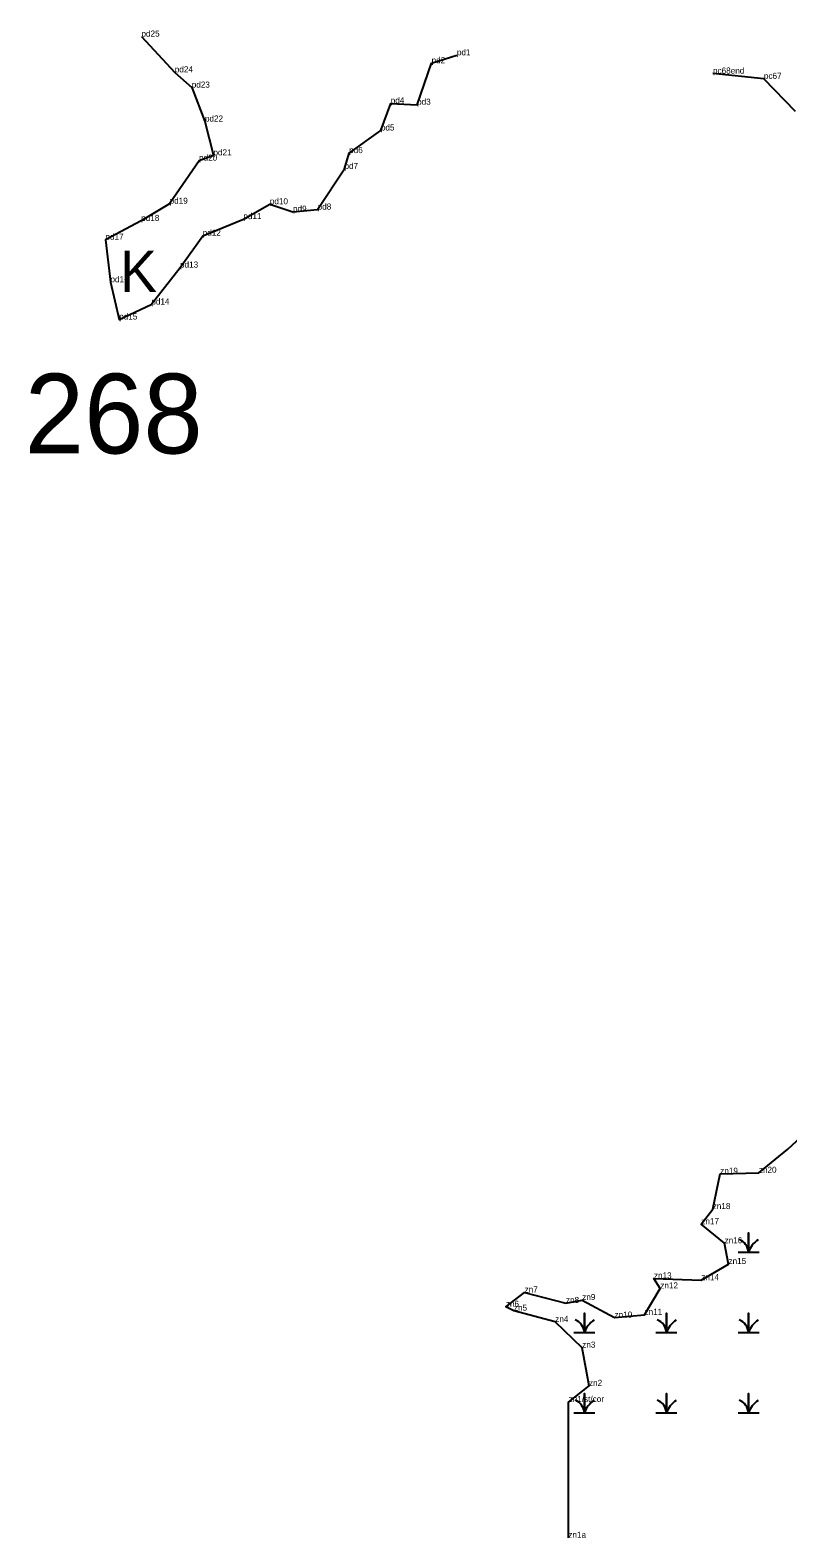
# Model space of a CAD drawing. Extents: x 2072529 to 2268796, y 436423 to 470406.
# Drawn here: x 2229846 to 2230467, y 437834 to 439069 of the extents above; entities that cross this region are included whole.
import ezdxf

# ---------------------------------------------------------------- set-up
doc = ezdxf.new("R2010")
doc.units = 0
for name, color, linetype in [('Default', 7, 'Continuous'), ('Exist Environmental Wetland Boundary', 7, 'Continuous'), ('Exist Environmental Wetland Boundary Cogo Comment', 7, 'Continuous'), ('Exist Hydro Swamp or Marsh', 7, 'Continuous'), ('Old_Level_20', 7, 'Continuous')]:
    doc.layers.add(name, color=color, linetype=linetype)

msp = doc.modelspace()

# ---------------------------------------------------------------- linework, layer by layer
at = {"layer": 'Exist Environmental Wetland Boundary'}
for points in [[(2229937.4, 439063.6), (2229964.7, 439034.3), (2229978.6, 439021.8), (2229989.4, 438994), (2229996.4, 438966.3), (2229984.6, 438962), (2229960.5, 438926.7), (2229937.2, 438912.6), (2229907.9, 438897.3), (2229912, 438862.4), (2229919.2, 438831.9), (2229945.5, 438844.2), (2229969, 438874.4), (2229987.6, 438900.5), (2230020.9, 438914.1), (2230042.6, 438926.3), (2230061.6, 438920.2), (2230081.8, 438921.9), (2230103.8, 438955.2), (2230107.6, 438968.2), (2230133.6, 438986.7), (2230141.7, 439008.9), (2230163.3, 439007.8), (2230175.2, 439041.8), (2230195.9, 439048.3)], [(2230473.4, 439002.4), (2230447.5, 439029), (2230405.8, 439033.3)], [(2230287.3, 437834.1), (2230287.5, 437945.3), (2230304.2, 437958.5), (2230298.6, 437989.8), (2230276.5, 438010.9), (2230242.6, 438020.1), (2230236, 438023.3), (2230251.4, 438035), (2230285.3, 438026.4), (2230298.6, 438028.8), (2230325.1, 438014.4), (2230349.7, 438016.7), (2230362.6, 438038.3), (2230357.4, 438046.5), (2230396.2, 438045.1), (2230418.5, 438058.3), (2230415.3, 438075.3), (2230396.2, 438090.9), (2230405.6, 438103.3), (2230411.7, 438132.2), (2230443.4, 438133), (2230467, 438152.3), (2230495.7, 438178.9)]]:
    msp.add_lwpolyline(points, dxfattribs=at)
at = {"layer": 'Exist Hydro Swamp or Marsh'}
for points in [[(2230426.3, 438068), (2230434.9, 438068), (2230434.9, 438083.8), (2230434.9, 438068), (2230443.5, 438068)], [(2230291.8, 438002.2), (2230300.4, 438002.2), (2230300.4, 438018), (2230300.4, 438002.2), (2230309, 438002.2)], [(2230359, 438002.2), (2230367.6, 438002.2), (2230367.6, 438018), (2230367.6, 438002.2), (2230376.2, 438002.2)], [(2230426.3, 438002.2), (2230434.9, 438002.2), (2230434.9, 438018), (2230434.9, 438002.2), (2230443.5, 438002.2)], [(2230291.8, 437936.4), (2230300.4, 437936.4), (2230300.4, 437952.2), (2230300.4, 437936.4), (2230309, 437936.4)], [(2230359, 437936.4), (2230367.6, 437936.4), (2230367.6, 437952.2), (2230367.6, 437936.4), (2230376.2, 437936.4)], [(2230426.3, 437936.4), (2230434.9, 437936.4), (2230434.9, 437952.2), (2230434.9, 437936.4), (2230443.5, 437936.4)]]:
    msp.add_lwpolyline(points, dxfattribs=at)
for centre, radius, start, end in [((2230422.6, 438067.1), 12.3, 4.1403, 67.535), ((2230453.1, 438061.9), 19.2, 122.1274, 161.6222), ((2230288.1, 438001.3), 12.3, 4.1403, 67.535), ((2230318.6, 437996.1), 19.2, 122.1274, 161.6222), ((2230355.4, 438001.3), 12.3, 4.1403, 67.535), ((2230385.9, 437996.1), 19.2, 122.1274, 161.6222), ((2230422.6, 438001.3), 12.3, 4.1403, 67.535), ((2230453.1, 437996.1), 19.2, 122.1274, 161.6222), ((2230288.1, 437935.5), 12.3, 4.1403, 67.535), ((2230318.6, 437930.3), 19.2, 122.1274, 161.6222), ((2230355.4, 437935.5), 12.3, 4.1403, 67.535), ((2230385.9, 437930.3), 19.2, 122.1274, 161.6222), ((2230422.6, 437935.5), 12.3, 4.1403, 67.535), ((2230453.1, 437930.3), 19.2, 122.1274, 161.6222)]:
    msp.add_arc(centre, radius, start, end, dxfattribs=at)
at = {"layer": 'Old_Level_20'}
for p, q in [((2229937.4, 439063.6), (2229937.4, 439063.6)), ((2230195.9, 439048.3), (2230195.9, 439048.3)), ((2230175.2, 439041.8), (2230175.2, 439041.8)), ((2229964.7, 439034.3), (2229964.7, 439034.3)), ((2230405.8, 439033.3), (2230405.8, 439033.3)), ((2230447.5, 439029), (2230447.5, 439029)), ((2229978.6, 439021.8), (2229978.6, 439021.8)), ((2230141.7, 439008.9), (2230141.7, 439008.9)), ((2230163.3, 439007.8), (2230163.3, 439007.8)), ((2229989.4, 438994), (2229989.4, 438994)), ((2230133.6, 438986.7), (2230133.6, 438986.7)), ((2229984.6, 438962), (2229984.6, 438962)), ((2229996.4, 438966.3), (2229996.4, 438966.3)), ((2230107.6, 438968.2), (2230107.6, 438968.2)), ((2230103.8, 438955.2), (2230103.8, 438955.2)), ((2229960.5, 438926.7), (2229960.5, 438926.7)), ((2230042.6, 438926.3), (2230042.6, 438926.3)), ((2229937.2, 438912.6), (2229937.2, 438912.6)), ((2230020.9, 438914.1), (2230020.9, 438914.1)), ((2230061.6, 438920.2), (2230061.6, 438920.2)), ((2230081.8, 438921.9), (2230081.8, 438921.9)), ((2229987.6, 438900.5), (2229987.6, 438900.5)), ((2229907.9, 438897.3), (2229907.9, 438897.3)), ((2229969, 438874.4), (2229969, 438874.4)), ((2229912, 438862.4), (2229912, 438862.4)), ((2229945.5, 438844.2), (2229945.5, 438844.2)), ((2229919.2, 438831.9), (2229919.2, 438831.9)), ((2230467, 438152.3), (2230467, 438152.3)), ((2230411.7, 438132.2), (2230411.7, 438132.2)), ((2230443.4, 438133), (2230443.4, 438133)), ((2230405.6, 438103.3), (2230405.6, 438103.3)), ((2230396.2, 438090.9), (2230396.2, 438090.9)), ((2230415.3, 438075.3), (2230415.3, 438075.3)), ((2230418.5, 438058.3), (2230418.5, 438058.3)), ((2230251.4, 438035), (2230251.4, 438035)), ((2230357.4, 438046.5), (2230357.4, 438046.5)), ((2230362.6, 438038.3), (2230362.6, 438038.3)), ((2230396.2, 438045.1), (2230396.2, 438045.1)), ((2230236, 438023.3), (2230236, 438023.3)), ((2230285.3, 438026.4), (2230285.3, 438026.4)), ((2230298.6, 438028.8), (2230298.6, 438028.8)), ((2230242.6, 438020.1), (2230242.6, 438020.1)), ((2230276.5, 438010.9), (2230276.5, 438010.9)), ((2230325.1, 438014.4), (2230325.1, 438014.4)), ((2230349.7, 438016.7), (2230349.7, 438016.7)), ((2230298.6, 437989.8), (2230298.6, 437989.8)), ((2230304.2, 437958.5), (2230304.2, 437958.5)), ((2230287.5, 437945.3), (2230287.5, 437945.3)), ((2230287.3, 437834.1), (2230287.3, 437834.1))]:
    msp.add_line(p, q, dxfattribs=at)

# ---------------------------------------------------------------- texts
at = {"layer": 'Default'}
msp.add_text('268', height=65.34, dxfattribs=at).set_placement((2229841.8, 438722.2))
at = {"layer": 'Exist Environmental Wetland Boundary Cogo Comment'}
for s, p in [('pd25', (2229937.4, 439063.6)), ('pd2', (2230175.2, 439041.8)), ('pd1', (2230195.9, 439048.3)), ('pd24', (2229964.7, 439034.3)), ('pc68end', (2230405.8, 439033.3)), ('pd23', (2229978.6, 439021.8)), ('pc67', (2230447.5, 439029)), ('pd4', (2230141.7, 439008.9)), ('pd3', (2230163.3, 439007.8)), ('pd22', (2229989.4, 438994)), ('pd5', (2230133.6, 438986.7)), ('pd6', (2230107.6, 438968.2)), ('pd20', (2229984.6, 438962)), ('pd21', (2229996.4, 438966.3)), ('pd7', (2230103.8, 438955.2)), ('pd19', (2229960.5, 438926.7)), ('pd10', (2230042.6, 438926.3)), ('pd9', (2230061.6, 438920.2)), ('pd8', (2230081.8, 438921.9)), ('pd18', (2229937.2, 438912.6)), ('pd11', (2230020.9, 438914.1)), ('pd17', (2229907.9, 438897.3)), ('pd12', (2229987.6, 438900.5)), ('pd13', (2229969, 438874.4)), ('pd16', (2229912, 438862.4)), ('pd14', (2229945.5, 438844.2)), ('pd15', (2229919.2, 438831.9)), ('zn19', (2230411.7, 438132.2)), ('zn20', (2230443.4, 438133)), ('zn18', (2230405.6, 438103.3)), ('zn17', (2230396.2, 438090.9)), ('zn16', (2230415.3, 438075.3)), ('zn15', (2230418.5, 438058.3)), ('zn13', (2230357.4, 438046.5)), ('zn14', (2230396.2, 438045.1)), ('zn7', (2230251.4, 438035)), ('zn12', (2230362.6, 438038.3)), ('zn6', (2230236, 438023.3)), ('zn5', (2230242.6, 438020.1)), ('zn8', (2230285.3, 438026.4)), ('zn9', (2230298.6, 438028.8)), ('zn4', (2230276.5, 438010.9)), ('zn10', (2230325.1, 438014.4)), ('zn11', (2230349.7, 438016.7)), ('zn3', (2230298.6, 437989.8)), ('zn2', (2230304.2, 437958.5)), ('zn1/st/cor', (2230287.5, 437945.3)), ('zn1a', (2230287.3, 437834.1))]:
    msp.add_text(s, height=5, dxfattribs=at).set_placement(p)
at = {"layer": 'Exist Hydro Swamp or Marsh'}
msp.add_text('K', height=34, dxfattribs=at).set_placement((2229919.9, 438854.4))

doc.saveas('drawing.dxf')
